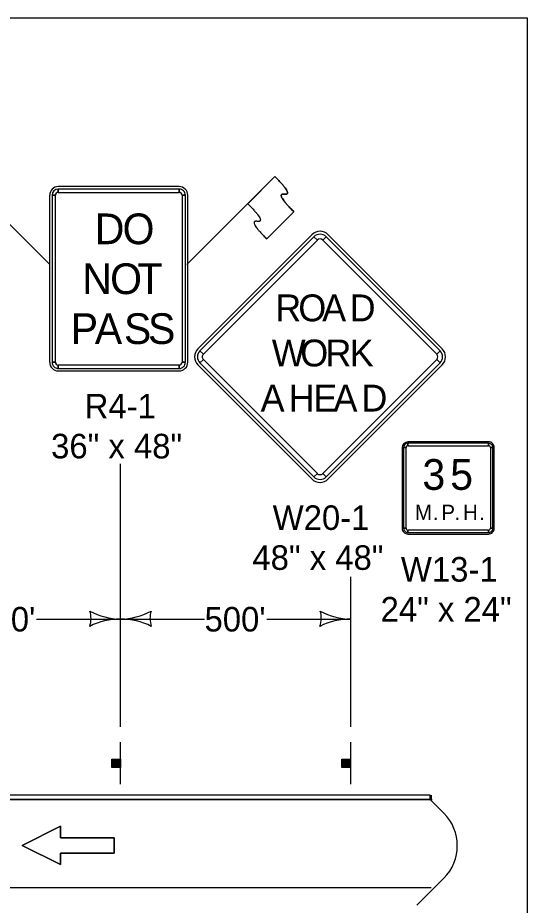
# Model space of a CAD drawing. Extents: x -2134934 to -2122394, y -2139046 to -2137036.
# Drawn here: x -2127429 to -2127097, y -2137614 to -2137036 of the extents above; entities that cross this region are included whole.
import ezdxf

# ---------------------------------------------------------------- set-up
doc = ezdxf.new("R2010")
doc.units = 0
for name, color, linetype in [('Barrier', 7, 'Continuous'), ('BridgeSuperStructureExisting', 7, 'Continuous'), ('Default', 7, 'Continuous'), ('DsnShtPlotIdentification', 7, 'Continuous'), ('TC_Barrier', 7, 'Continuous')]:
    doc.layers.add(name, color=color, linetype=linetype)

msp = doc.modelspace()

# ---------------------------------------------------------------- linework, layer by layer
at = {"layer": 'Barrier'}
for p, q in [((-2127407.97, -2137196.68), (-2127465.31, -2137139.38)), ((-2127318.68, -2137196.68), (-2127261.36, -2137139.36)), ((-2127261.36, -2137139.36), (-2127279.05, -2137157.04)), ((-2127323.73, -2137145.92), (-2127402.48, -2137145.92)), ((-2127408.11, -2137151.54), (-2127408.11, -2137260.29)), ((-2127406.54, -2137151.54), (-2127404.36, -2137151.54)), ((-2127402.48, -2137149.67), (-2127402.48, -2137147.48)), ((-2127323.73, -2137147.48), (-2127323.73, -2137149.67)), ((-2127321.86, -2137151.54), (-2127319.67, -2137151.54)), ((-2127318.11, -2137260.29), (-2127318.11, -2137151.54)), ((-2127266.66, -2137180.03), (-2127248.99, -2137162.35)), ((-2127237.26, -2137177.23), (-2127311.51, -2137251.47)), ((-2127235.93, -2137178.55), (-2127233.72, -2137180.76)), ((-2127230.19, -2137180.76), (-2127227.98, -2137178.55)), ((-2127152.41, -2137251.47), (-2127226.65, -2137177.23)), ((-2127307.97, -2137255.01), (-2127310.18, -2137252.8)), ((-2127153.73, -2137252.8), (-2127155.94, -2137255.01)), ((-2127404.36, -2137260.29), (-2127406.54, -2137260.29)), ((-2127402.48, -2137264.35), (-2127402.48, -2137262.17)), ((-2127323.73, -2137262.17), (-2127323.73, -2137264.35)), ((-2127319.67, -2137260.29), (-2127321.86, -2137260.29)), ((-2127311.51, -2137262.08), (-2127237.26, -2137336.33)), ((-2127310.18, -2137260.75), (-2127307.97, -2137258.54)), ((-2127226.65, -2137336.33), (-2127152.41, -2137262.08)), ((-2127155.94, -2137258.54), (-2127153.73, -2137260.75)), ((-2127402.48, -2137265.92), (-2127323.73, -2137265.92)), ((-2127122.19, -2137312.17), (-2127174.69, -2137312.17)), ((-2127174.69, -2137314.67), (-2127174.69, -2137313.1)), ((-2127122.19, -2137313.1), (-2127122.19, -2137314.67)), ((-2127178.44, -2137315.92), (-2127178.44, -2137368.42)), ((-2127177.5, -2137315.92), (-2127175.94, -2137315.92)), ((-2127120.94, -2137315.92), (-2127119.37, -2137315.92)), ((-2127118.44, -2137368.42), (-2127118.44, -2137315.92)), ((-2127233.72, -2137332.79), (-2127235.93, -2137335)), ((-2127227.98, -2137335), (-2127230.19, -2137332.79)), ((-2127175.94, -2137368.42), (-2127177.5, -2137368.42)), ((-2127174.69, -2137371.23), (-2127174.69, -2137369.67)), ((-2127174.69, -2137372.17), (-2127122.19, -2137372.17)), ((-2127122.19, -2137369.67), (-2127122.19, -2137371.23)), ((-2127119.37, -2137368.42), (-2127120.94, -2137368.42))]:
    msp.add_line(p, q, dxfattribs=at)
for points in [[(-2127406.54, -2137151.54), (-2127406.54, -2137260.29), (-2127404.36, -2137260.29), (-2127404.36, -2137151.54), (-2127406.54, -2137151.54)], [(-2127323.73, -2137147.48), (-2127402.48, -2137147.48), (-2127402.48, -2137149.67), (-2127323.73, -2137149.67), (-2127323.73, -2137147.48)], [(-2127319.67, -2137260.29), (-2127319.67, -2137151.54), (-2127321.86, -2137151.54), (-2127321.86, -2137260.29), (-2127319.67, -2137260.29)], [(-2127235.93, -2137178.55), (-2127310.18, -2137252.8), (-2127307.97, -2137255.01), (-2127233.72, -2137180.76), (-2127235.93, -2137178.55)], [(-2127153.73, -2137252.8), (-2127227.98, -2137178.55), (-2127230.19, -2137180.76), (-2127155.94, -2137255.01), (-2127153.73, -2137252.8)], [(-2127402.48, -2137264.35), (-2127323.73, -2137264.35), (-2127323.73, -2137262.17), (-2127402.48, -2137262.17), (-2127402.48, -2137264.35)], [(-2127310.18, -2137260.75), (-2127235.93, -2137335), (-2127233.72, -2137332.79), (-2127307.97, -2137258.54), (-2127310.18, -2137260.75)], [(-2127227.98, -2137335), (-2127153.73, -2137260.75), (-2127155.94, -2137258.54), (-2127230.19, -2137332.79), (-2127227.98, -2137335)], [(-2127122.19, -2137313.1), (-2127174.69, -2137313.1), (-2127174.69, -2137314.67), (-2127122.19, -2137314.67), (-2127122.19, -2137313.1)], [(-2127177.5, -2137315.92), (-2127177.5, -2137368.42), (-2127175.94, -2137368.42), (-2127175.94, -2137315.92), (-2127177.5, -2137315.92)], [(-2127119.37, -2137368.42), (-2127119.37, -2137315.92), (-2127120.94, -2137315.92), (-2127120.94, -2137368.42), (-2127119.37, -2137368.42)], [(-2127174.69, -2137371.23), (-2127122.19, -2137371.23), (-2127122.19, -2137369.67), (-2127174.69, -2137369.67), (-2127174.69, -2137371.23)]]:
    msp.add_lwpolyline(points, close=True, dxfattribs=at)
for centre, radius, start, end in [((-2127402.48, -2137151.54), 5.62, 90.00021, 179.99985), ((-2127323.73, -2137151.54), 5.62, 0, 90.00021), ((-2127402.48, -2137151.54), 4.06, 90.00021, 179.99985), ((-2127402.48, -2137151.54), 1.87, 90.00021, 179.99985), ((-2127323.73, -2137151.54), 4.06, 0, 90.00021), ((-2127323.73, -2137151.54), 1.87, 0, 90.00021), ((-2127231.96, -2137182.53), 7.5, 44.99999, 134.99974), ((-2127231.96, -2137182.53), 5.62, 44.99999, 134.99974), ((-2127231.96, -2137182.53), 2.5, 44.99999, 134.99974), ((-2127306.2, -2137256.78), 7.5, 134.99974, 224.99995), ((-2127306.2, -2137256.78), 5.62, 134.99974, 224.99995), ((-2127306.2, -2137256.78), 2.5, 134.99974, 224.99995), ((-2127157.71, -2137256.78), 2.5, 315.00016, 44.9998), ((-2127157.71, -2137256.78), 5.62, 315.00016, 44.9998), ((-2127157.71, -2137256.78), 7.5, 315.00016, 44.9998), ((-2127402.48, -2137260.29), 5.62, 179.99985, 270.00006), ((-2127402.48, -2137260.29), 4.06, 179.99985, 270.00006), ((-2127402.48, -2137260.29), 1.87, 179.99985, 270.00006), ((-2127323.73, -2137260.29), 5.62, 270.00006, 0.00027), ((-2127323.73, -2137260.29), 4.06, 270.00006, 0.00027), ((-2127323.73, -2137260.29), 1.87, 270.00006, 0.00027), ((-2127174.69, -2137315.92), 3.75, 90.00021, 179.99985), ((-2127174.69, -2137315.92), 2.81, 90.00021, 179.99985), ((-2127122.19, -2137315.92), 3.75, 0, 90.00021), ((-2127122.19, -2137315.92), 2.81, 0, 90.00021), ((-2127174.69, -2137315.92), 1.25, 90.00021, 179.99985), ((-2127122.19, -2137315.92), 1.25, 0, 90.00021), ((-2127231.96, -2137331.02), 7.5, 224.99995, 315.00016), ((-2127231.96, -2137331.02), 5.62, 224.99995, 315.00016), ((-2127231.96, -2137331.02), 2.5, 224.99995, 315.00016), ((-2127174.69, -2137368.42), 3.75, 179.99985, 270.00006), ((-2127174.69, -2137368.42), 2.81, 179.99985, 270.00006), ((-2127174.69, -2137368.42), 1.25, 179.99985, 270.00006), ((-2127122.19, -2137368.42), 3.75, 270.00006, 0.00027), ((-2127122.19, -2137368.42), 2.81, 270.00006, 0.00027), ((-2127122.19, -2137368.42), 1.25, 270.00006, 0.00027)]:
    msp.add_arc(centre, radius, start, end, dxfattribs=at)
for points in [[(-2127248.99, -2137162.35), (-2127261.36, -2137149.98), (-2127248.99, -2137151.75), (-2127261.36, -2137139.36)], [(-2127279.05, -2137157.04), (-2127266.67, -2137169.43), (-2127279.04, -2137167.66), (-2127266.66, -2137180.03)]]:
    msp.add_open_spline(points, degree=2, dxfattribs=at)
at = {"layer": 'BridgeSuperStructureExisting'}
for p, q in [((-2127361.96, -2137497.66), (-2127361.96, -2137326.42)), ((-2127211.96, -2137497.66), (-2127211.96, -2137399.97)), ((-2127416.71, -2137427.66), (-2127361.96, -2137427.66)), ((-2127361.96, -2137427.66), (-2127307.21, -2137427.66)), ((-2127266.71, -2137427.66), (-2127211.96, -2137427.66)), ((-2127361.96, -2137535.16), (-2127361.96, -2137507.66)), ((-2127211.96, -2137535.16), (-2127211.96, -2137507.66)), ((-2127367.28, -2137524.3), (-2127367.28, -2137518.71)), ((-2127366.96, -2137518.71), (-2127366.96, -2137524.3)), ((-2127366.74, -2137524.3), (-2127366.74, -2137518.71)), ((-2127366.42, -2137518.71), (-2127366.42, -2137524.3)), ((-2127366.19, -2137524.3), (-2127366.21, -2137518.71)), ((-2127365.78, -2137518.71), (-2127365.76, -2137524.3)), ((-2127365.56, -2137524.3), (-2127365.56, -2137518.71)), ((-2127365.13, -2137518.71), (-2127365.13, -2137524.3)), ((-2127364.75, -2137524.3), (-2127364.75, -2137518.71)), ((-2127364.43, -2137518.71), (-2127364.41, -2137524.3)), ((-2127364.21, -2137524.3), (-2127364.21, -2137518.71)), ((-2127363.94, -2137518.71), (-2127363.94, -2137524.3)), ((-2127363.61, -2137524.3), (-2127363.61, -2137518.71)), ((-2127363.4, -2137518.71), (-2127363.4, -2137524.3)), ((-2127363.18, -2137524.3), (-2127363.18, -2137518.71)), ((-2127362.91, -2137518.71), (-2127362.91, -2137524.3)), ((-2127362.65, -2137524.3), (-2127362.65, -2137518.71)), ((-2127362.37, -2137518.71), (-2127362.37, -2137524.3)), ((-2127217.28, -2137524.3), (-2127217.28, -2137518.71)), ((-2127216.96, -2137518.71), (-2127216.96, -2137524.3)), ((-2127216.74, -2137524.3), (-2127216.74, -2137518.71)), ((-2127216.42, -2137518.71), (-2127216.42, -2137524.3)), ((-2127216.2, -2137524.3), (-2127216.21, -2137518.71)), ((-2127215.78, -2137518.71), (-2127215.76, -2137524.3)), ((-2127215.56, -2137524.3), (-2127215.56, -2137518.71)), ((-2127215.13, -2137518.71), (-2127215.13, -2137524.3)), ((-2127214.75, -2137524.3), (-2127214.75, -2137518.71)), ((-2127214.43, -2137518.71), (-2127214.41, -2137524.3)), ((-2127214.21, -2137524.3), (-2127214.21, -2137518.71)), ((-2127213.94, -2137518.71), (-2127213.94, -2137524.3)), ((-2127213.61, -2137524.3), (-2127213.61, -2137518.71)), ((-2127213.4, -2137518.71), (-2127213.4, -2137524.3)), ((-2127213.18, -2137524.3), (-2127213.18, -2137518.71)), ((-2127212.91, -2137518.71), (-2127212.91, -2137524.3)), ((-2127212.65, -2137524.3), (-2127212.65, -2137518.71)), ((-2127212.37, -2137518.71), (-2127212.37, -2137524.3)), ((-2127160.12, -2137545.16), (-2128660.12, -2137545.16)), ((-2127160.12, -2137545.16), (-2127151.33, -2137553.95)), ((-2127151.33, -2137553.95), (-2127160.12, -2137545.16)), ((-2127168.91, -2137613.95), (-2127151.33, -2137596.37)), ((-2127151.33, -2137596.38), (-2127168.9, -2137613.95))]:
    msp.add_line(p, q, dxfattribs=at)
for points in [[(-2127362.05, -2137518.71), (-2127362.05, -2137524.34), (-2127367.68, -2137524.34), (-2127367.68, -2137518.71)], [(-2127212.05, -2137518.71), (-2127212.05, -2137524.34), (-2127217.68, -2137524.34), (-2127217.68, -2137518.71)], [(-2127366.01, -2137579.99), (-2127366.01, -2137569.99), (-2127401.01, -2137569.99), (-2127401.01, -2137562.49), (-2127426.01, -2137574.99), (-2127401.01, -2137587.49), (-2127401.01, -2137579.99)]]:
    msp.add_lwpolyline(points, close=True, dxfattribs=at)
msp.add_lwpolyline([(-2127401.01, -2137579.99), (-2127401.01, -2137587.49), (-2127426.01, -2137574.99), (-2127401.01, -2137562.49), (-2127401.01, -2137569.99), (-2127366.01, -2137569.99), (-2127366.01, -2137579.99), (-2127401.01, -2137579.99)], dxfattribs=at)
for centre, radius, start, end in [((-2127397.57, -2137427.04), 16.42, 341.26665, 16.73335), ((-2127361.2, -2137385.17), 42.5, 240.92751, 268.9824), ((-2127362.71, -2137385.17), 42.5, 271.0176, 299.07249), ((-2127326.34, -2137427.04), 16.42, 163.26665, 198.73335), ((-2127247.57, -2137427.04), 16.42, 341.26665, 16.73335), ((-2127211.2, -2137385.17), 42.5, 240.92751, 268.9824), ((-2127362.68, -2137470.15), 42.5, 89.0176, 117.07249), ((-2127361.23, -2137470.15), 42.5, 62.92751, 90.9824), ((-2127212.68, -2137470.15), 42.5, 89.0176, 117.07249), ((-2127172.55, -2137575.16), 30, 315, 45), ((-2127172.55, -2137575.16), 30, 315, 45)]:
    msp.add_arc(centre, radius, start, end, dxfattribs=at)
at = {"layer": 'Default'}
msp.add_lwpolyline([(-2130231.95, -2137035.95), (-2127096.96, -2137035.95), (-2127096.96, -2139045.94), (-2130231.95, -2139045.94)], close=True, dxfattribs=at)
at = {"layer": 'DsnShtPlotIdentification'}
for p, q in [((-2127160.12, -2137542.16), (-2128660.12, -2137542.16)), ((-2127160.12, -2137542.16), (-2128660.12, -2137542.16)), ((-2127160.12, -2137545.16), (-2128660.12, -2137545.16)), ((-2127805.12, -2137545.16), (-2127160.12, -2137545.16)), ((-2127160.12, -2137545.16), (-2127160.12, -2137542.16)), ((-2127159.5, -2137542.16), (-2127159.5, -2137545.16)), ((-2127159.45, -2137602.66), (-2127811.95, -2137602.66))]:
    msp.add_line(p, q, dxfattribs=at)
msp.add_lwpolyline([(-2128471.26, -2137545.16), (-2127158.8, -2137545.16)], dxfattribs=at)
at = {"layer": 'TC_Barrier'}
msp.add_line((-2127248.99, -2137162.35), (-2127266.66, -2137180.03), dxfattribs=at)
for points in [[(-2127261.36, -2137139.36), (-2127248.99, -2137151.75), (-2127261.36, -2137149.98), (-2127248.99, -2137162.35)], [(-2127279.05, -2137157.04), (-2127266.67, -2137169.43), (-2127279.04, -2137167.66), (-2127266.66, -2137180.03)]]:
    msp.add_open_spline(points, degree=2, dxfattribs=at)

# ---------------------------------------------------------------- texts
at = {"layer": 'Barrier'}
for s, height, p in [('D', 20, (-2127378.73, -2137183.42)), ('O', 20, (-2127360.61, -2137183.42)), ('N', 20, (-2127386.86, -2137215.92)), ('O', 20, (-2127368.73, -2137215.92)), ('T', 20, (-2127350.92, -2137215.92)), ('R', 17.5, (-2127261.12, -2137233.65)), ('O', 17.5, (-2127246.11, -2137233.65)), ('A', 17.5, (-2127230.56, -2137233.65)), ('D', 17.5, (-2127212.68, -2137233.65)), ('P', 20, (-2127394.37, -2137248.42)), ('A', 20, (-2127378.69, -2137248.42)), ('S', 20, (-2127359.72, -2137248.42)), ('S', 20, (-2127344.03, -2137248.42)), ('W', 17.5, (-2127263.4, -2137263.03)), ('O', 17.5, (-2127244.81, -2137263.03)), ('R', 17.5, (-2127228.4, -2137263.03)), ('K', 17.5, (-2127212.54, -2137263.03)), ('A', 17.5, (-2127270.68, -2137292.4)), ('H', 17.5, (-2127252.47, -2137292.4)), ('E', 17.5, (-2127236.24, -2137292.4)), ('A', 17.5, (-2127223.2, -2137292.4)), ('D', 17.5, (-2127204.99, -2137292.4)), ('R4-1', 16, (-2127385.27, -2137296.92)), ('36" x 48"', 16, (-2127407.17, -2137322.92)), ('3', 20, (-2127165.29, -2137343.41)), ('5', 20, (-2127147.16, -2137343.41)), ('W20-1', 16, (-2127262.81, -2137369.52)), ('M', 10, (-2127170.21, -2137363.1)), ('P', 10, (-2127152.96, -2137363.1)), ('H', 10, (-2127138.84, -2137363.1)), ('.', 10, (-2127158.42, -2137363.1)), ('.', 10, (-2127144.3, -2137363.1)), ('.', 10, (-2127128.37, -2137363.1)), ('48" x 48"', 16, (-2127276.02, -2137395.52)), ('W13-1', 16, (-2127179.29, -2137403.17)), ('24" x 24"', 16, (-2127192.5, -2137429.17))]:
    msp.add_text(s, height=height, dxfattribs=at).set_placement(p)
at = {"layer": 'BridgeSuperStructureExisting'}
for p in [(-2127457.21, -2137435.66), (-2127307.21, -2137435.66)]:
    msp.add_text("500'", height=16, dxfattribs=at).set_placement(p)

doc.saveas('drawing.dxf')
